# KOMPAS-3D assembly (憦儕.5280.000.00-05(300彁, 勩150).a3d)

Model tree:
1. Плоскость XY
2. Плоскость ZX
3. Плоскость ZY
4. Ось X
5. Ось Y
6. Ось Z
7. Начало координат  (labels: Операция без истории:1; Операция без истории:2; Операция без истории:3; ␣įȁ0)

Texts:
  Линия-выноска #1
  Линия-выноска #2
  Линия-выноска #3
  Отклонения формы и база
  Марка координационной оси
  Марка/позиционное обозначение с линией-выноской
  Марка/позиционное обозначение на линии
  Марка/позиционное обозначение без линии-выноски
